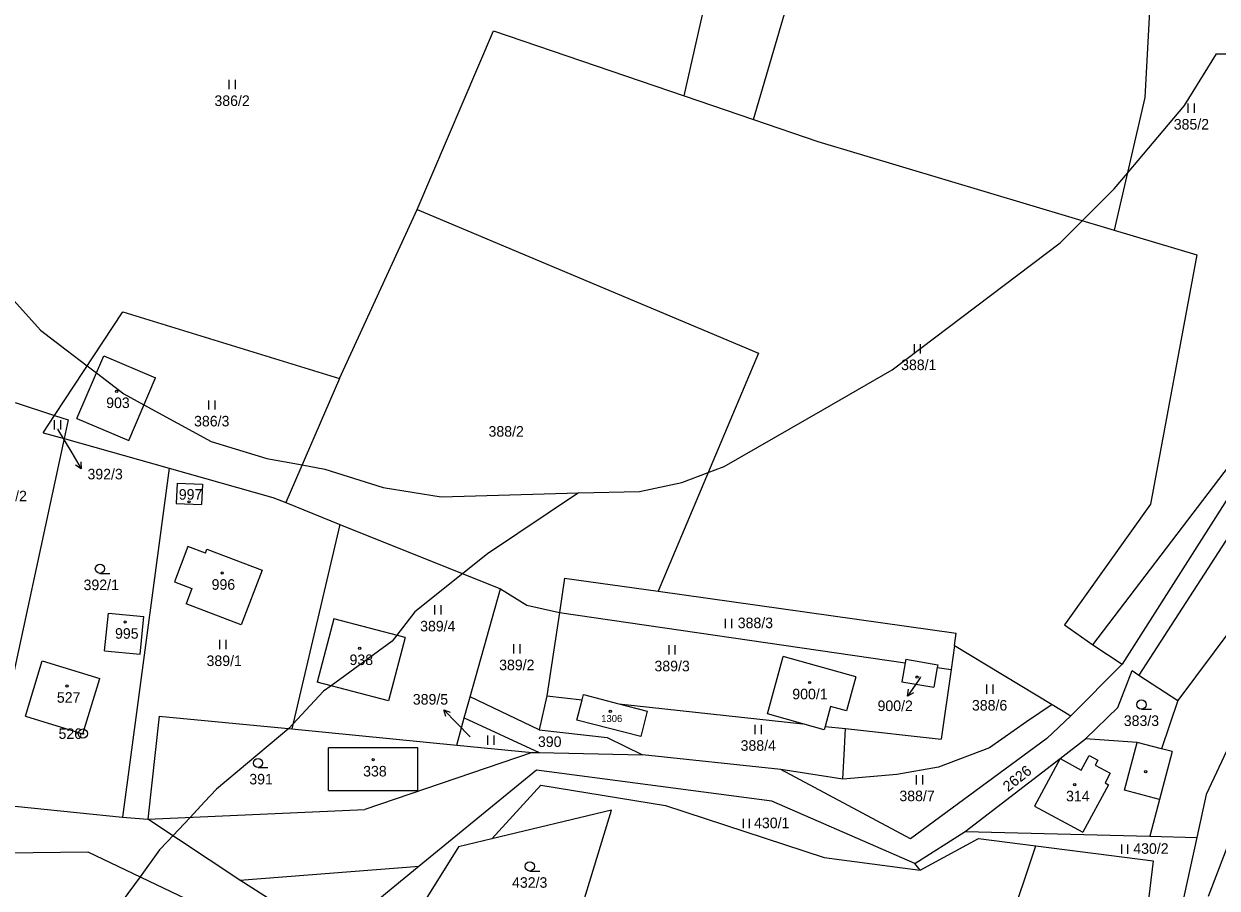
# Model space of a CAD drawing. Extents: x -439246 to -433691, y -1130252 to -1121148.
# Drawn here: x -437381 to -437188.8, y -1124134.4 to -1123995.2 of the extents above; entities that cross this region are included whole.
import ezdxf

# ---------------------------------------------------------------- set-up
doc = ezdxf.new("R2010")
doc.units = 0
for name, color, linetype in [('Vrstva 1', 7, 'Continuous'), ('Vrstva 16', 7, 'Continuous'), ('Vrstva 17', 7, 'Continuous'), ('Vrstva 18', 7, 'Continuous'), ('Vrstva 19', 7, 'Continuous'), ('Vrstva 24', 7, 'Continuous'), ('Vrstva 25', 7, 'Continuous'), ('Vrstva 3', 7, 'Continuous'), ('Vrstva 37', 7, 'Continuous'), ('Vrstva 4', 7, 'Continuous'), ('Vrstva 52', 7, 'Continuous')]:
    doc.layers.add(name, color=color, linetype=linetype)

msp = doc.modelspace()

# ---------------------------------------------------------------- linework, layer by layer
at = {"layer": 'Vrstva 1'}
for points in [[(-437274.66, -1124006.79), (-437259.78, -1123940.99)], [(-437263.5, -1124010.6), (-437243.91, -1123943.9)], [(-437198.19, -1123965.25), (-437200.43, -1124007.06)], [(-437317.69, -1124025.07), (-437305.37, -1123996.31)], [(-437305.37, -1123996.31), (-437274.66, -1124006.79)], [(-437274.66, -1124006.79), (-437263.5, -1124010.6)], [(-437200.43, -1124007.06), (-437205.38, -1124028.4)], [(-437263.5, -1124010.6), (-437253.13, -1124014.13)], [(-437253.13, -1124014.13), (-437205.38, -1124028.4)], [(-437330.19, -1124052.32), (-437317.69, -1124025.07)], [(-437317.69, -1124025.07), (-437262.69, -1124048.22)], [(-437205.38, -1124028.4), (-437192.08, -1124032.37)], [(-437192.08, -1124032.37), (-437199.54, -1124072.58)], [(-437376.09, -1124058.26), (-437365.11, -1124041.59)], [(-437365.11, -1124041.59), (-437330.19, -1124052.32)], [(-437262.69, -1124048.22), (-437278.85, -1124086.59)], [(-437372.47, -1124058.76), (-437368.16, -1124048.64)], [(-437368.16, -1124048.64), (-437359.83, -1124052.19)], [(-437364.14, -1124062.31), (-437359.83, -1124052.19)], [(-437174.79, -1124052.25), (-437204.09, -1124098.33)], [(-437330.19, -1124052.32), (-437338.85, -1124072.31)], [(-437382.45, -1124056.19), (-437376.09, -1124058.26)], [(-437377.92, -1124061.04), (-437376.09, -1124058.26)], [(-437376.09, -1124058.26), (-437373.89, -1124058.98)], [(-437373.89, -1124058.98), (-437374.54, -1124061.99)], [(-437372.47, -1124058.76), (-437364.14, -1124062.31)], [(-437377.92, -1124061.04), (-437374.54, -1124061.99)], [(-437374.54, -1124061.99), (-437384.94, -1124110.07)], [(-437374.54, -1124061.99), (-437357.64, -1124066.76)], [(-437357.64, -1124066.76), (-437365.12, -1124122.97)], [(-437357.64, -1124066.76), (-437340.93, -1124071.48)], [(-437208.84, -1124095.22), (-437186.78, -1124066.3)], [(-437356.35, -1124069.16), (-437356.49, -1124072.45)], [(-437356.35, -1124069.16), (-437352.26, -1124069.33)], [(-437352.26, -1124069.33), (-437352.4, -1124072.63)], [(-437340.93, -1124071.48), (-437338.85, -1124072.31)], [(-437356.49, -1124072.45), (-437352.4, -1124072.63)], [(-437338.85, -1124072.31), (-437330.11, -1124075.81)], [(-437199.54, -1124072.58), (-437213.36, -1124092)], [(-437330.11, -1124075.81), (-437337.86, -1124108.76)], [(-437330.11, -1124075.81), (-437304.23, -1124086.18)], [(-437185.67, -1124075.77), (-437201.39, -1124100.1)], [(-437354.59, -1124079.38), (-437356.75, -1124085.08)], [(-437351.78, -1124080.45), (-437354.59, -1124079.38)], [(-437351.78, -1124080.45), (-437351.53, -1124079.8)], [(-437351.53, -1124079.8), (-437342.66, -1124083.18)], [(-437342.66, -1124083.18), (-437346.02, -1124092.01)], [(-437293.93, -1124084.47), (-437294.76, -1124090.01)], [(-437293.93, -1124084.47), (-437278.85, -1124086.59)], [(-437356.75, -1124085.08), (-437353.95, -1124086.15)], [(-437353.95, -1124086.15), (-437354.89, -1124088.63)], [(-437309.12, -1124103.61), (-437304.23, -1124086.18)], [(-437304.23, -1124086.18), (-437299.98, -1124088.82)], [(-437278.85, -1124086.59), (-437230.81, -1124093.32)], [(-437346.02, -1124092.01), (-437354.89, -1124088.63)], [(-437368.03, -1124096.16), (-437367.42, -1124090.09)], [(-437367.42, -1124090.09), (-437361.7, -1124090.66)], [(-437362.31, -1124096.73), (-437361.7, -1124090.66)], [(-437299.98, -1124088.82), (-437294.76, -1124090.01)], [(-437294.76, -1124090.01), (-437296.77, -1124103.45)], [(-437294.76, -1124090.01), (-437239.03, -1124098.12)], [(-437177.04, -1124090.51), (-437190.55, -1124119.33)], [(-437331.08, -1124091.02), (-437333.76, -1124101.22)], [(-437319.58, -1124094.04), (-437331.08, -1124091.02)], [(-437213.36, -1124092), (-437208.84, -1124095.22)], [(-437186.4, -1124092.55), (-437195.14, -1124104.2)], [(-437319.58, -1124094.04), (-437322.26, -1124104.24)], [(-437231.1, -1124095.33), (-437230.81, -1124093.32)], [(-437368.03, -1124096.16), (-437362.31, -1124096.73)], [(-437231.1, -1124095.33), (-437231.65, -1124099.19)], [(-437231.1, -1124095.33), (-437215.36, -1124104.82)], [(-437208.84, -1124095.22), (-437204.09, -1124098.33)], [(-437380.78, -1124106.71), (-437378.07, -1124097.81)], [(-437378.07, -1124097.81), (-437368.81, -1124100.63)], [(-437261.25, -1124106.35), (-437258.68, -1124097.12)], [(-437246.98, -1124100.38), (-437258.68, -1124097.12)], [(-437239.03, -1124098.12), (-437239.57, -1124101.15)], [(-437238.93, -1124097.51), (-437239.03, -1124098.12)], [(-437238.93, -1124097.51), (-437233.81, -1124098.42)], [(-437212.34, -1124106.65), (-437204.09, -1124098.33)], [(-437233.89, -1124098.87), (-437234.45, -1124102.06)], [(-437233.81, -1124098.42), (-437233.89, -1124098.87)], [(-437233.89, -1124098.87), (-437231.65, -1124099.19)], [(-437231.65, -1124099.19), (-437233.25, -1124110.4)], [(-437204.81, -1124105.33), (-437202.5, -1124099.37)], [(-437202.5, -1124099.37), (-437201.39, -1124100.1)], [(-437201.39, -1124100.1), (-437195.14, -1124104.2)], [(-437371.52, -1124109.53), (-437368.81, -1124100.63)], [(-437322.26, -1124104.24), (-437333.76, -1124101.22)], [(-437246.98, -1124100.38), (-437248.5, -1124105.87)], [(-437239.57, -1124101.15), (-437234.45, -1124102.06)], [(-437310.07, -1124106.98), (-437309.12, -1124103.61)], [(-437298.02, -1124108.91), (-437309.12, -1124103.61)], [(-437296.77, -1124103.45), (-437298.02, -1124108.91)], [(-437296.77, -1124103.45), (-437291.1, -1124104.07)], [(-437291.95, -1124107.34), (-437291.1, -1124104.07)], [(-437291.1, -1124104.07), (-437290.89, -1124103.24)], [(-437290.89, -1124103.24), (-437285.16, -1124104.72)], [(-437285.16, -1124104.72), (-437280.59, -1124105.9)], [(-437285.16, -1124104.72), (-437255.52, -1124107.96)], [(-437280.59, -1124105.9), (-437281.64, -1124109.99)], [(-437251.06, -1124105.16), (-437251.94, -1124108.35)], [(-437248.5, -1124105.87), (-437251.06, -1124105.16)], [(-437215.36, -1124104.82), (-437219.48, -1124107.64)], [(-437215.36, -1124104.82), (-437212.34, -1124106.65)], [(-437210.02, -1124110.37), (-437204.81, -1124105.33)], [(-437195.14, -1124104.2), (-437197.73, -1124111.98)], [(-437380.78, -1124106.71), (-437371.52, -1124109.53)], [(-437359.22, -1124106.68), (-437361.08, -1124123.31)], [(-437359.22, -1124106.68), (-437337.86, -1124108.76)], [(-437311.3, -1124111.35), (-437310.07, -1124106.98)], [(-437310.07, -1124106.98), (-437298.02, -1124112.56)], [(-437281.64, -1124109.99), (-437291.95, -1124107.34)], [(-437255.52, -1124107.96), (-437261.25, -1124106.35)], [(-437252.1, -1124108.92), (-437255.52, -1124107.96)], [(-437219.48, -1124107.64), (-437225.48, -1124111.78)], [(-437212.34, -1124106.65), (-437216.23, -1124110.28)], [(-437337.86, -1124108.76), (-437311.3, -1124111.35)], [(-437298.02, -1124108.91), (-437287.08, -1124110.14)], [(-437251.94, -1124108.35), (-437252.1, -1124108.92)], [(-437251.94, -1124108.35), (-437248.65, -1124108.71)], [(-437248.82, -1124111.94), (-437248.65, -1124108.71)], [(-437248.65, -1124108.71), (-437233.25, -1124110.4)], [(-437317.56, -1124111.8), (-437331.97, -1124111.8)], [(-437331.97, -1124118.7), (-437331.97, -1124111.8)], [(-437317.56, -1124118.7), (-437317.56, -1124111.8)], [(-437311.3, -1124111.35), (-437299.15, -1124112.54)], [(-437287.08, -1124110.14), (-437281.35, -1124112.95)], [(-437216.23, -1124110.28), (-437238.17, -1124126.45)], [(-437225.48, -1124111.78), (-437233.68, -1124114.93)], [(-437214.1, -1124113.55), (-437210.02, -1124110.37)], [(-437201.69, -1124110.94), (-437210.02, -1124110.37)], [(-437197.73, -1124111.98), (-437201.69, -1124110.94)], [(-437299.15, -1124112.54), (-437326.08, -1124121.76)], [(-437299.15, -1124112.54), (-437298.02, -1124112.56)], [(-437298.02, -1124112.56), (-437281.35, -1124112.95)], [(-437259.1, -1124115.3), (-437281.35, -1124112.95)], [(-437249.07, -1124116.88), (-437248.82, -1124111.94)], [(-437229.37, -1124125.29), (-437214.1, -1124113.55)], [(-437196.06, -1124112.42), (-437198.09, -1124120.11)], [(-437196.06, -1124112.42), (-437197.73, -1124111.98)], [(-437298.45, -1124115.39), (-437317.32, -1124130.86)], [(-437260.55, -1124120.39), (-437298.45, -1124115.39)], [(-437249.07, -1124116.88), (-437259.1, -1124115.3)], [(-437238.17, -1124126.45), (-437259.1, -1124115.3)], [(-437233.68, -1124114.93), (-437240.39, -1124116.08)], [(-437240.39, -1124116.08), (-437249.07, -1124116.88)], [(-437331.97, -1124118.7), (-437317.56, -1124118.7)], [(-437305.62, -1124126.45), (-437297.75, -1124117.8)], [(-437297.75, -1124117.8), (-437277.64, -1124121.08)], [(-437190.55, -1124119.33), (-437192.07, -1124126.25)], [(-437387.24, -1124120.71), (-437365.12, -1124122.97)], [(-437277.64, -1124121.08), (-437252.09, -1124129.47)], [(-437237.49, -1124130.42), (-437260.55, -1124120.39)], [(-437198.09, -1124120.11), (-437199.65, -1124126.06)], [(-437365.12, -1124122.97), (-437361.08, -1124123.31)], [(-437361.08, -1124123.31), (-437326.08, -1124121.76)], [(-437346.24, -1124133.12), (-437361.08, -1124123.31)], [(-437286.35, -1124121.87), (-437305.62, -1124126.45)], [(-437298.53, -1124161.75), (-437286.35, -1124121.87)], [(-437190.18, -1124135.71), (-437184.96, -1124122.11)], [(-437237.49, -1124130.42), (-437229.37, -1124125.29)], [(-437229.37, -1124125.29), (-437199.65, -1124126.06)], [(-437305.62, -1124126.45), (-437311, -1124127.73)], [(-437236.64, -1124131.49), (-437227.21, -1124126.4)], [(-437227.21, -1124126.4), (-437217.98, -1124127.59)], [(-437192.07, -1124126.25), (-437200.45, -1124164.39)], [(-437199.65, -1124126.06), (-437192.07, -1124126.25)], [(-437397.14, -1124128.88), (-437370.75, -1124128.54)], [(-437370.75, -1124128.54), (-437348.82, -1124139.01)], [(-437311, -1124127.73), (-437323.25, -1124147.35)], [(-437218.51, -1124129.2), (-437217.98, -1124127.59)], [(-437217.98, -1124127.59), (-437199.08, -1124130.03)], [(-437346.24, -1124133.12), (-437317.32, -1124130.86)], [(-437317.32, -1124130.86), (-437331.54, -1124142.52)], [(-437252.09, -1124129.47), (-437236.64, -1124131.49)], [(-437236.64, -1124131.49), (-437237.49, -1124130.42)], [(-437232.42, -1124170.71), (-437218.51, -1124129.2)], [(-437199.08, -1124130.03), (-437203.09, -1124162.98)], [(-437331.54, -1124142.52), (-437346.24, -1124133.12)]]:
    msp.add_lwpolyline(points, dxfattribs=at)
at = {"layer": 'Vrstva 16'}
for p, q in [((-437373.31, -1124064.28), (-437371.78, -1124066.86)), ((-437236.98, -1124101), (-437238.65, -1124103.49)), ((-437311.29, -1124107.85), (-437313.39, -1124105.7))]:
    msp.add_line(p, q, dxfattribs=at)
for points in [[(-437375.59, -1124060.45), (-437373.31, -1124064.28)], [(-437371.86, -1124065.74), (-437371.78, -1124066.86), (-437372.72, -1124066.25)], [(-437236.58, -1124100.41), (-437236.98, -1124101)], [(-437237.68, -1124102.94), (-437238.65, -1124103.49), (-437238.51, -1124102.38)], [(-437313.04, -1124106.77), (-437313.39, -1124105.7), (-437312.33, -1124106.07)], [(-437309.15, -1124110.05), (-437311.29, -1124107.85)]]:
    msp.add_lwpolyline(points, dxfattribs=at)
at = {"layer": 'Vrstva 24'}
for radius in [0.75, 0.1]:
    msp.add_circle((-437371.51, -1124109.52), radius, dxfattribs=at)
at = {"layer": 'Vrstva 25'}
for p, q in [((-437347.94, -1124005.71), (-437347.94, -1124004.21)), ((-437346.94, -1124005.71), (-437346.94, -1124004.21)), ((-437193.43, -1124009.51), (-437193.43, -1124008.01)), ((-437192.43, -1124009.51), (-437192.43, -1124008.01)), ((-437237.56, -1124048.26), (-437237.56, -1124046.76)), ((-437236.56, -1124048.26), (-437236.56, -1124046.76)), ((-437351.22, -1124057.33), (-437351.22, -1124055.83)), ((-437350.22, -1124057.33), (-437350.22, -1124055.83)), ((-437376.1, -1124060.54), (-437376.1, -1124059.04)), ((-437375.1, -1124060.54), (-437375.1, -1124059.04)), ((-437368.77, -1124083.7), (-437367.17, -1124083.7)), ((-437314.82, -1124090.35), (-437314.82, -1124088.85)), ((-437313.82, -1124090.35), (-437313.82, -1124088.85)), ((-437268, -1124092.53), (-437268, -1124091.03)), ((-437267, -1124092.53), (-437267, -1124091.03)), ((-437349.46, -1124095.93), (-437349.46, -1124094.43)), ((-437348.46, -1124095.93), (-437348.46, -1124094.43)), ((-437302.1, -1124096.6), (-437302.1, -1124095.1)), ((-437301.1, -1124096.6), (-437301.1, -1124095.1)), ((-437277.08, -1124096.78), (-437277.08, -1124095.28)), ((-437276.08, -1124096.78), (-437276.08, -1124095.28)), ((-437225.89, -1124103.1), (-437225.89, -1124101.6)), ((-437224.89, -1124103.1), (-437224.89, -1124101.6)), ((-437200.99, -1124105.59), (-437199.39, -1124105.59)), ((-437306.27, -1124111.33), (-437306.27, -1124109.83)), ((-437305.27, -1124111.33), (-437305.27, -1124109.83)), ((-437263.2, -1124109.58), (-437263.2, -1124108.08)), ((-437262.2, -1124109.58), (-437262.2, -1124108.08)), ((-437343.31, -1124115), (-437341.71, -1124115)), ((-437237.2, -1124117.7), (-437237.2, -1124116.2)), ((-437236.2, -1124117.7), (-437236.2, -1124116.2)), ((-437265.11, -1124124.75), (-437265.11, -1124123.25)), ((-437264.11, -1124124.75), (-437264.11, -1124123.25)), ((-437204.17, -1124128.88), (-437204.17, -1124127.38)), ((-437203.17, -1124128.88), (-437203.17, -1124127.38)), ((-437299.53, -1124131.65), (-437297.93, -1124131.65))]:
    msp.add_line(p, q, dxfattribs=at)
for centre, radius in [((-437366.07, -1124054.37), 0.175), ((-437354.42, -1124072.18), 0.175), ((-437368.77, -1124082.95), 0.75), ((-437349.09, -1124083.64), 0.175), ((-437364.7, -1124091.53), 0.175), ((-437326.92, -1124095.77), 0.175), ((-437237.14, -1124100.41), 0.175), ((-437374.08, -1124101.84), 0.175), ((-437254.45, -1124101.29), 0.175), ((-437200.99, -1124104.84), 0.75), ((-437286.56, -1124105.94), 0.175), ((-437343.31, -1124114.25), 0.75), ((-437324.75, -1124113.72), 0.175), ((-437200.3, -1124115.64), 0.175), ((-437211.73, -1124117.73), 0.175), ((-437299.53, -1124130.9), 0.75)]:
    msp.add_circle(centre, radius, dxfattribs=at)
at = {"layer": 'Vrstva 3'}
for points in [[(-437372.47, -1124058.76), (-437368.16, -1124048.64)], [(-437368.16, -1124048.64), (-437359.83, -1124052.19)], [(-437364.14, -1124062.31), (-437359.83, -1124052.19)], [(-437372.47, -1124058.76), (-437364.14, -1124062.31)], [(-437356.35, -1124069.16), (-437356.49, -1124072.45)], [(-437356.35, -1124069.16), (-437352.26, -1124069.33)], [(-437352.26, -1124069.33), (-437352.4, -1124072.63)], [(-437356.49, -1124072.45), (-437352.4, -1124072.63)], [(-437354.59, -1124079.38), (-437356.75, -1124085.08)], [(-437351.78, -1124080.45), (-437354.59, -1124079.38)], [(-437351.78, -1124080.45), (-437351.53, -1124079.8)], [(-437351.53, -1124079.8), (-437342.66, -1124083.18)], [(-437342.66, -1124083.18), (-437346.02, -1124092.01)], [(-437356.75, -1124085.08), (-437353.95, -1124086.15)], [(-437353.95, -1124086.15), (-437354.89, -1124088.63)], [(-437346.02, -1124092.01), (-437354.89, -1124088.63)], [(-437368.03, -1124096.16), (-437367.42, -1124090.09)], [(-437367.42, -1124090.09), (-437361.7, -1124090.66)], [(-437362.31, -1124096.73), (-437361.7, -1124090.66)], [(-437331.08, -1124091.02), (-437333.76, -1124101.22)], [(-437319.58, -1124094.04), (-437331.08, -1124091.02)], [(-437319.58, -1124094.04), (-437322.26, -1124104.24)], [(-437368.03, -1124096.16), (-437362.31, -1124096.73)], [(-437380.78, -1124106.71), (-437378.07, -1124097.81)], [(-437378.07, -1124097.81), (-437368.81, -1124100.63)], [(-437261.25, -1124106.35), (-437258.68, -1124097.12)], [(-437246.98, -1124100.38), (-437258.68, -1124097.12)], [(-437239.03, -1124098.12), (-437239.57, -1124101.15)], [(-437238.93, -1124097.51), (-437239.03, -1124098.12)], [(-437238.93, -1124097.51), (-437233.81, -1124098.42)], [(-437233.89, -1124098.87), (-437234.45, -1124102.06)], [(-437233.81, -1124098.42), (-437233.89, -1124098.87)], [(-437371.52, -1124109.53), (-437368.81, -1124100.63)], [(-437322.26, -1124104.24), (-437333.76, -1124101.22)], [(-437246.98, -1124100.38), (-437248.5, -1124105.87)], [(-437239.57, -1124101.15), (-437234.45, -1124102.06)], [(-437291.95, -1124107.34), (-437291.1, -1124104.07)], [(-437291.1, -1124104.07), (-437290.89, -1124103.24)], [(-437290.89, -1124103.24), (-437285.16, -1124104.72)], [(-437285.16, -1124104.72), (-437280.59, -1124105.9)], [(-437280.59, -1124105.9), (-437281.64, -1124109.99)], [(-437251.06, -1124105.16), (-437251.94, -1124108.35)], [(-437248.5, -1124105.87), (-437251.06, -1124105.16)], [(-437380.78, -1124106.71), (-437371.52, -1124109.53)], [(-437281.64, -1124109.99), (-437291.95, -1124107.34)], [(-437255.52, -1124107.96), (-437261.25, -1124106.35)], [(-437252.1, -1124108.92), (-437255.52, -1124107.96)], [(-437251.94, -1124108.35), (-437252.1, -1124108.92)], [(-437317.56, -1124111.8), (-437331.97, -1124111.8)], [(-437331.97, -1124118.7), (-437331.97, -1124111.8)], [(-437317.56, -1124118.7), (-437317.56, -1124111.8)], [(-437214.1, -1124113.55), (-437218.22, -1124121.19)], [(-437214.1, -1124113.55), (-437210.67, -1124115.4)], [(-437210.67, -1124115.4), (-437209.4, -1124113.04)], [(-437209.4, -1124113.04), (-437208.01, -1124113.79)], [(-437208.01, -1124113.79), (-437208.43, -1124114.59)], [(-437208.43, -1124114.59), (-437206, -1124115.9)], [(-437206, -1124115.9), (-437206.84, -1124117.46)], [(-437206.84, -1124117.46), (-437206.28, -1124117.77)], [(-437331.97, -1124118.7), (-437317.56, -1124118.7)], [(-437206.28, -1124117.77), (-437210.4, -1124125.41)], [(-437218.22, -1124121.19), (-437210.4, -1124125.41)]]:
    msp.add_lwpolyline(points, dxfattribs=at)
at = {"layer": 'Vrstva 37'}
for centre in [(-437366.07, -1124054.37), (-437354.42, -1124072.18), (-437349.09, -1124083.64), (-437364.7, -1124091.53), (-437326.92, -1124095.77), (-437237.14, -1124100.41), (-437374.08, -1124101.84), (-437254.45, -1124101.29), (-437286.56, -1124105.94), (-437324.75, -1124113.72), (-437211.73, -1124117.73)]:
    msp.add_circle(centre, 0.175, dxfattribs=at)
at = {"layer": 'Vrstva 4'}
for points in [[(-437203.72, -1124118.63), (-437201.69, -1124110.94)], [(-437214.1, -1124113.55), (-437218.22, -1124121.19)], [(-437214.1, -1124113.55), (-437210.67, -1124115.4)], [(-437210.67, -1124115.4), (-437209.4, -1124113.04)], [(-437209.4, -1124113.04), (-437208.01, -1124113.79)], [(-437208.01, -1124113.79), (-437208.43, -1124114.59)], [(-437208.43, -1124114.59), (-437206, -1124115.9)], [(-437206, -1124115.9), (-437206.84, -1124117.46)], [(-437206.84, -1124117.46), (-437206.28, -1124117.77)], [(-437206.28, -1124117.77), (-437210.4, -1124125.41)], [(-437198.09, -1124120.11), (-437203.72, -1124118.63)], [(-437218.22, -1124121.19), (-437210.4, -1124125.41)]]:
    msp.add_lwpolyline(points, dxfattribs=at)
at = {"layer": 'Vrstva 52'}
for points in [[(-437406.3, -1123991.62), (-437405.41, -1123995.41), (-437404.33, -1124000), (-437403.28, -1124003.78), (-437402.84, -1124005.35), (-437400.07, -1124014.93), (-437391.76, -1124029.63), (-437378.34, -1124044.54), (-437374.22, -1124047.69), (-437370.83, -1124050.27), (-437369.34, -1124051.4), (-437364.92, -1124054.77), (-437361.68, -1124056.54), (-437350.86, -1124062.44), (-437341.91, -1124065.21), (-437336.22, -1124066.24), (-437332.54, -1124066.91), (-437323.17, -1124069.89), (-437313.79, -1124071.38), (-437291.65, -1124070.71)], [(-437291.65, -1124070.71), (-437281.84, -1124070.53), (-437275.02, -1124069.04), (-437270.79, -1124067.45), (-437269.66, -1124067.03), (-437268.2, -1124066.49), (-437252.31, -1124057.35), (-437241.15, -1124050.93), (-437214.1, -1124030.48), (-437210.49, -1124026.87), (-437207.41, -1124023.8), (-437205.36, -1124021.75), (-437203.25, -1124019.25), (-437194.07, -1124008.33), (-437188.89, -1124000), (-437184, -1124000)], [(-437291.65, -1124070.71), (-437306.34, -1124080.55), (-437310.33, -1124083.74), (-437318.05, -1124089.92), (-437320.96, -1124093.68), (-437321.67, -1124094.6), (-437331.53, -1124101.8), (-437332.75, -1124102.7), (-437337.68, -1124108.01), (-437338.29, -1124108.66), (-437338.35, -1124108.71), (-437350.01, -1124118.46), (-437351.94, -1124120.53), (-437354.25, -1124123.01), (-437357.03, -1124125.98), (-437357.88, -1124126.89), (-437359.17, -1124128.26), (-437362.32, -1124132.57), (-437367.16, -1124139.19), (-437375.16, -1124150.12), (-437376, -1124151.27), (-437377.49, -1124154.68), (-437379.1, -1124156.78), (-437387.93, -1124168.31)]]:
    msp.add_lwpolyline(points, dxfattribs=at)

# ---------------------------------------------------------------- texts
at = {"layer": 'Vrstva 16'}
for s, p in [('392/3', (-437370.78, -1124068.56)), ('389/5', (-437318.37, -1124104.84)), ('900/2', (-437243.5, -1124105.88))]:
    msp.add_text(s, height=1.7, dxfattribs=at).set_placement(p)
at = {"layer": 'Vrstva 17'}
msp.add_text('526', height=1.7, dxfattribs=at).set_placement((-437375.44, -1124110.37))
at = {"layer": 'Vrstva 18'}
for s, height, p in [('386/2', 1.7, (-437350.33, -1124008.41)), ('385/2', 1.7, (-437195.78, -1124012.21)), ('388/1', 1.7, (-437239.7, -1124050.96)), ('386/3', 1.7, (-437353.61, -1124060.03)), ('388/2', 1.7, (-437306.17, -1124061.68)), ('392/3', 0.1, (-437375.78, -1124060.45)), ('392/2', 1.7, (-437386.23, -1124072.09)), ('392/1', 1.7, (-437371.41, -1124086.4)), ('389/4', 1.7, (-437317.19, -1124093.05)), ('388/3', 1.7, (-437266.02, -1124092.53)), ('389/1', 1.7, (-437351.6, -1124098.63)), ('389/2', 1.7, (-437304.46, -1124099.3)), ('389/3', 1.7, (-437279.44, -1124099.48)), ('388/6', 1.7, (-437228.29, -1124105.8)), ('383/3', 1.7, (-437203.83, -1124108.29)), ('390', 1.7, (-437298.21, -1124111.66)), ('389/5', 0.1, (-437309.34, -1124110.05)), ('388/4', 1.7, (-437265.56, -1124112.28)), ('391', 1.7, (-437344.71, -1124117.7)), ('388/7', 1.7, (-437239.98, -1124120.4)), ('430/1', 1.7, (-437263.39, -1124124.75)), ('430/2', 1.7, (-437202.3, -1124128.88)), ('432/3', 1.7, (-437302.38, -1124134.35))]:
    msp.add_text(s, height=height, dxfattribs=at).set_placement(p)
msp.add_text('2626', height=1.7, rotation=38.5214, dxfattribs=at).set_placement((-437222.46, -1124118.97))
at = {"layer": 'Vrstva 19'}
for s, height, p in [('903', 1.7, (-437367.77, -1124057.07)), ('997', 1.7, (-437356.07, -1124071.83)), ('996', 1.7, (-437350.78, -1124086.34)), ('995', 1.7, (-437366.34, -1124094.23)), ('938', 1.7, (-437328.56, -1124098.47)), ('900/2', 0.1, (-437236.78, -1124100.41)), ('900/1', 1.7, (-437257.23, -1124103.99)), ('527', 1.7, (-437375.71, -1124104.54)), ('1306', 1.14, (-437288.02, -1124107.65)), ('338', 1.7, (-437326.37, -1124116.42)), ('314', 1.7, (-437213.13, -1124120.43))]:
    msp.add_text(s, height=height, dxfattribs=at).set_placement(p)

doc.saveas('drawing.dxf')
